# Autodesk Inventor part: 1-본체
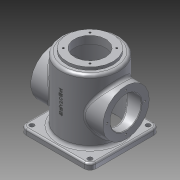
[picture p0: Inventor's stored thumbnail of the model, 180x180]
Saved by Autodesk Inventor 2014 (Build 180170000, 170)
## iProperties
Created: 2015-10
Part Number: 1-본체
Material: 알루미늄 6061
Document SubType Name: Modeling
Designer: Administrator
Density: 2.71 g/cm^3
Appearance: 알루미늄 - 평지
Mass: 984.861 g
Surface Area: 1041.28 cm^2
Volume: 363.417 cm^3
Author: Administrator
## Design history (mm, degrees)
sketch "스케치1"
  geometry: C1 r 50 at (0, 0); 1 further point
  constraints: 1 centre point, 1 coincident
  dimensions: "d0" = 100 diameter of C1
extrude "돌출1" new body sketch "스케치1" distance "d1" = 120; taper "d2" = 0 deg
sketch "스케치2"
  geometry: C1 r 40 at (0, 0); 1 further point
  constraints: 1 centre point, 1 coincident
  dimensions: "d3" = 80 diameter of C1
extrude "돌출2" join sketch "스케치2" distance "d4" = 5 (computed from d1); taper "d5" = 0 deg
sketch "스케치4"
  geometry: L1 (-60, 60)-(60, 60); L2 (60, 60)-(60, -60); L3 (60, -60)-(-60, -60); L4 (-60, -60)-(-60, 60); 3 further points
  constraints: 8 end point, 2 midpoint, 2 parallel, 2 perpendicular, 1 horizontal, 1 horizontal alignment, 1 vertical alignment
  dimensions: "d28" = 120 distance of L1.start L1.end
extrude "돌출4" join sketch "스케치4" distance "d29" = 10; taper "d30" = 0 deg
sketch "스케치8"
  geometry: C1 r 40 at (0, 60); 1 further point
  constraints: 1 centre point, 1 vertical alignment
  dimensions: "d39" = 80 diameter of C1; "d40" = 60 distance of point (0, 0) C1.centre
extrude "돌출5" join sketch "스케치8" stored distance "d41" = 124; taper "d42" = 0 deg
node "작업 평면4"
sketch "스케치10"
  geometry: L1 (-3.002, 49.261)-(-3.002, 90.739); L2 (-3.002, 90.739)-(3.002, 90.739); L3 (3.002, 90.739)-(3.002, 49.261); L4 (3.002, 49.261)-(-3.002, 49.261); L5 (60, 0)-(-60, 0) reference; 4 further points
  constraints: 3 midpoint, 1 vertical alignment, 2 other
  dimensions: "d43" = 70 distance from line of L5 point (-3.002, 70)
feature "엠보싱2" sketch "스케치10" dims "d39" = 80, "d40" = 60, "d44" = 0.5, "d45" = 0
hole "구멍3" diameter "d48" = 54; stored, may be unused: countersink angle "d52" = 90 deg, drill point angle "d54" = 118 deg; dims "d46" = 10, "d47" = 10, "d49" = 6, "d50" = 90, "d51" = 112, "d53" = 8
hole "구멍4" diameter "d57" = 54; stored, may be unused: countersink angle "d61" = 90 deg, drill point angle "d63" = 118 deg; dims "d58" = 6, "d59" = 90, "d60" = 112, "d62" = 8, "d64" = 10, "d65" = 10
fillet "모깎기2" dims "d66" = 10
fillet "모깎기3" dims "d67" = 5
fillet "모깎기4" dims "d68" = 3
chamfer "모따기1" distance "d69" = 3; stored, may be unused: second distance "d70" = 2, angle "d71" = 45 deg
sketch "스케치11"
  geometry: L1 (0, 0)-(-32.5, 0); L2 (60, -50)-(60, 50) reference; 1 further point
  constraints: 2 end point, 1 horizontal, 1 horizontal alignment
  dimensions: "d72" = 32.5 distance of L1.start L1.end; "d73" = 60 distance from line of L1.start L2
hole "구멍5" sketch "스케치11" at (-32.5, 0) diameter "d74" = 3.242; stored, may be unused: countersink angle "d78" = 90 deg, drill point angle "d80" = 118 deg; dims "d75" = 8, "d76" = 90, "d77" = 112, "d79" = 10
sketch "스케치12"
  geometry: L1 (0, 0)-(-22.981, 22.981); L2 (0, -84)-(0, 84) reference
  constraints: 2 end point
  dimensions: "d85" = 45 deg angle of L2 L1; "d86" = 32.5 distance of L1.start L1.end
hole "구멍6" sketch "스케치12" at (-22.981, 22.981) diameter "d87" = 3.242; stored, may be unused: countersink angle "d91" = 90 deg, drill point angle "d93" = 118 deg; dims "d88" = 8, "d89" = 90, "d90" = 112, "d92" = 10
chamfer "모따기2" distance "d97" = 1; stored, may be unused: second distance "d98" = 2, angle "d99" = 45 deg
fillet "모깎기5" dims "d100" = 3
hole "구멍7" diameter "d103" = 8; stored, may be unused: countersink angle "d107" = 90 deg, drill point angle "d109" = 118 deg; dims "d101" = 10, "d102" = 10, "d104" = 8, "d105" = 90, "d106" = 112, "d108" = 10
hole "구멍8" diameter "d112" = 8; stored, may be unused: countersink angle "d116" = 90 deg, drill point angle "d118" = 118 deg; dims "d110" = 10, "d111" = 10, "d113" = 8, "d114" = 90, "d115" = 112, "d117" = 10
hole "구멍9" diameter "d121" = 8; stored, may be unused: countersink angle "d125" = 90 deg, drill point angle "d127" = 118 deg; dims "d119" = 10, "d120" = 10, "d122" = 8, "d123" = 90, "d124" = 112, "d126" = 10
hole "구멍10" diameter "d130" = 8; stored, may be unused: countersink angle "d134" = 90 deg, drill point angle "d136" = 118 deg; dims "d128" = 10, "d129" = 10, "d131" = 8, "d132" = 90, "d133" = 112, "d135" = 10
node "솔리드1"
pattern_circular "원형 패턴1" dims angle "d82" = 360 deg
mirror "대칭1"
pattern_circular "원형 패턴2" dims angle "d95" = 360 deg
